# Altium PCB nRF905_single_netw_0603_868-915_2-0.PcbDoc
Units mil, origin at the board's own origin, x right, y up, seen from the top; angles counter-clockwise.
Board outline 720.03 x 705.03 mil, 2 copper layers (Top Layer, Bottom Layer); 19 components, 22 nets, 70 pads, 44 vias.
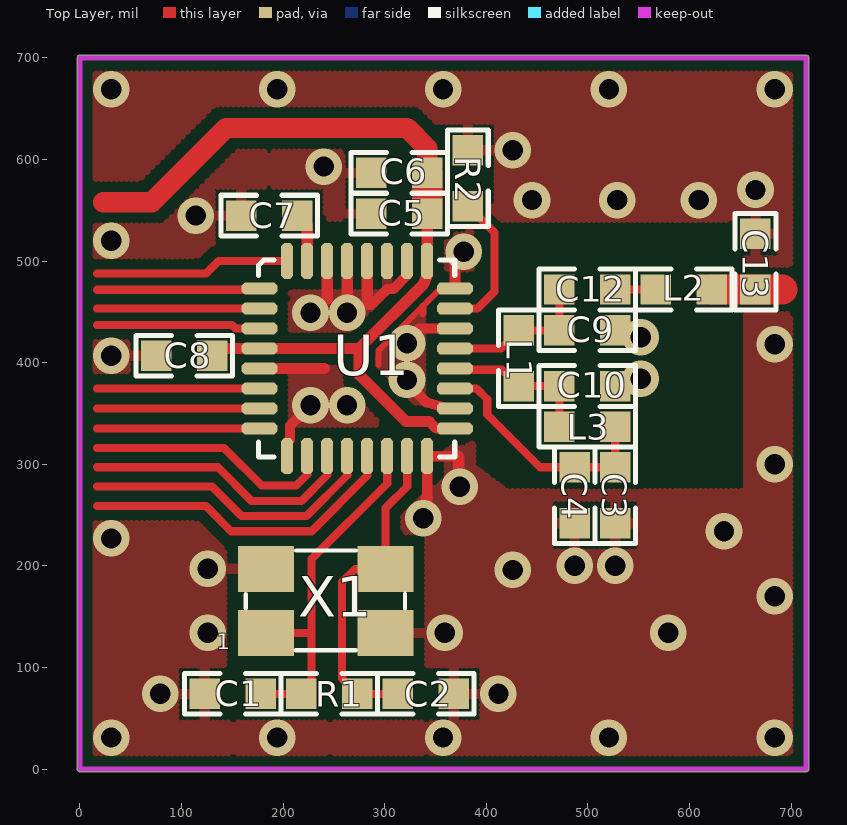
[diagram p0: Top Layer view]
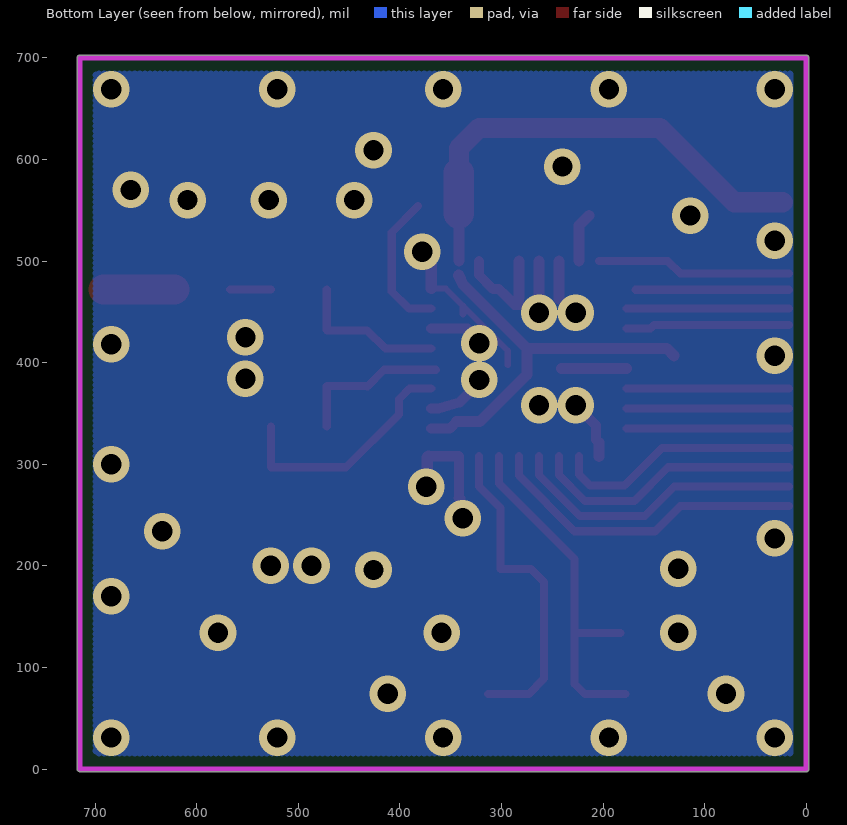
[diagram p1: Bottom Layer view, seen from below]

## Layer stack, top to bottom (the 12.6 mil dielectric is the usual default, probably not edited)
Top Layer: signal copper 1.4
Dielectric: core 12.6, FR-4, Dk 4.8
Bottom Layer: signal copper 1.4

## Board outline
-2.52,0 ccw(c0,0) 0,-2.52 715,-2.52 ccw(c715,0) 717.51,0 717.51,700 ccw(c715,700) 715,702.52 0,702.52 ccw(c0,700) -2.52,700

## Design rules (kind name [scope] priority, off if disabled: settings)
Clearance [All] p1: gap=6
ComponentClearance [All] p1: gap=10 collisioncheckmode=3 verticalgap=10
MinimumAnnularRing [All] p1: minimumring=8
PolygonConnect PolygonConnect_1 [IsVia And InNet(GND)] p1: connectstyle=Direct reliefconductorwidth=10 reliefentries=4 polygonreliefangle="90 Angle"
PolygonConnect [All] p2: connectstyle=Direct reliefconductorwidth=10 reliefentries=4 polygonreliefangle="90 Angle"
RoutingVias [All] p1: holewidth=20 width=36 viastyle="Through Hole" minholewidth=15 minwidth=30 maxholewidth=30 maxwidth=50
SolderMaskExpansion [All] p1: expansion=4
TestPointUsage [All] p1: valid=0 allowmultiple=FALSE
Testpoint [All] p1: side=15 testpointundercomponent=TRUE minsize=40 maxsize=100 preferedsize=60 minholesize=0 maxholesize=40 preferedholesize=32 testpointgrid=1 style=1023 order=0-112345678
Width [All] p1: maxlimit=30 minlimit=6 preferedwidth=6
18 further rules are at their usual default settings.

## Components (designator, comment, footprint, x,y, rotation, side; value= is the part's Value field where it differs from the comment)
C1 "22pF" 0603s#1 178,74 r180 top
C2 "22pF" 0603s#1 368,74 r180 top
C3 "33pF" 0603s#1 527,297 r270 top
C4 "3.3nF" 0603s#1 487,297 r270 top
C5 "33pF" 0603s#1 341.9,546.69 r180 top
C6 "4.7nF" 0603s#1 341.9,586.69 r180 top
C7 "10nF" 0603s#2 213.79,544.79 r180 top
C8 "33pF" 0603s#1 130.11,406.79 r180 top
C9 "5.6pF" 0603s#1 472,432 r0 top
C10 "5.6pF" 0603s#1 527,377 r180 top
C12 "22pF" 0603s#1 472,472 r0 top
C13 "4.7pF" 0603s#1 665,472 r90 top
L1 "12nH" 0603s#1 432,432 r270 top
L2 "10nH" 0603s#1 567,472 r0 top
L3 "12nH" 0603s#1 527,337 r180 top
R1 "1M" 0603s#1 218,74 r0 top
R2 "22K" 0603s#1 382,554 r90 top
U1 "nRF905" "QFN 5x5/32L" 273,404 r0 top
X1 "16 MHz" BT-XTAL 183,134 r0 top

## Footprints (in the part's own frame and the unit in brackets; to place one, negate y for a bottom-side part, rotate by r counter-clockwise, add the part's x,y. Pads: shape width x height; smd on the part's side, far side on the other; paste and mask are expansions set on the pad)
0603s#1 [mil]
  rect 30x30 smd: 1(0,0) 2(55,0)
  silkscreen extent -20,-20 75,20
0603s#2 [mil]
  rect 30x30 smd: 1(55,0) 2(0,0)
  silkscreen extent -20,-20 75,20
BT-XTAL [mm]
  rect 1.4x1.15 smd: 1(0,0) 2(2.996,0) 3(2.996,1.602) 4(0,1.602)
  silkscreen extent -0.5,-0.43 3.48,2.06
"QFN 5x5/32L" [mm]
  oct 0.9x0.3 smd: 1(-2.441,1.75) 2(-2.441,1.25) 3(-2.441,0.75) 4(-2.441,0.25) 5(-2.441,-0.25) 6(-2.441,-0.75) 7(-2.441,-1.25) 8(-2.441,-1.75) 17(2.441,-1.75) 18(2.441,-1.25) 19(2.441,-0.75) 20(2.441,-0.25) 21(2.441,0.25) 22(2.441,0.75) 23(2.441,1.25) 24(2.441,1.75)
  oct 0.3x0.9 smd: 9(-1.75,-2.441) 10(-1.25,-2.441) 11(-0.75,-2.441) 12(-0.25,-2.441) 13(0.25,-2.441) 14(0.75,-2.441) 15(1.25,-2.441) 16(1.75,-2.441) 25(1.75,2.441) 26(1.25,2.441) 27(0.75,2.441) 28(0.25,2.441) 29(-0.25,2.441) 30(-0.75,2.441) 31(-1.25,2.441) 32(-1.75,2.441)
  silkscreen extent -2.46,-2.46 2.44,2.46

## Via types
v1: diameter 36, hole 20, Top Layer to Bottom Layer, 44 vias

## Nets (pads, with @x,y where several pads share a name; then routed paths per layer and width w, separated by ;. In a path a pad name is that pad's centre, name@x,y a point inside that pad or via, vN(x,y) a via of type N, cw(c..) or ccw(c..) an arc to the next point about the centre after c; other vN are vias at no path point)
GND: C1.2 C2.1 C3.2 C4.2 C5.2 C6.2 C7.1 C8.2 C9.2 C10.1 C13.2 R2.2 U1.5 U1.9 U1.16 U1.18 U1.22 U1.24 U1.26 U1.27 U1.28 U1.29 U1.30 X1.2 X1.4 | length 687.7
  Top Layer w6: 293.84,397.66 293.84,411.84 354.9,472.9 U1.24
  Top Layer w7: 337.89,448.06 337.89,455.68
  Top Layer w10: U1.9@204.1,321.1 206.88,323.88 206.88,337.88 v1(227,358) ; 281,457 287.13,457 296.43,466.29 302.53,472.39 308.39,472.39 322.21,486.21 U1.26 ; v1@319,383 341,361 362,354.79 U1.18 ; v1@319,419 333.53,433.53 U1.22 ; 341.9,266.9 U1.16 372.11,307.89
  Top Layer w11: U1.5 240.84,394.16 ; U1.9 U1.9@204.1,321.1 ; 243.47,462.53 U1.30 ; v1@263.16,458.16 U1.29 ; 282.84,463.84 U1.28 ; 341,266 341.9,266.9 ; U1.24 369.11,500.11 v1(378,509) ; 372.11,307.89 373,307 v1@373,278
  other v1: 31,31 194.25,31 357.5,31 520.75,31 684,31 79,74 412,74 126,134 359,134 579,134 684,170 426,196 126,197.07 487,200 527,200 31,227 634,234 338,247 374,278 684,300 263,358 322,383 552,384 31,406.79 684,418 322,419 552,425 227,449 263,449 31,520 114.11,544.79 445,560 529,560 609,560 665,570 240,593 426,609 31,669 194.25,669 357.5,669 520.75,669 684,669
NetC1_1: C1.1 R1.1 U1.14 X1.1 | length 354
  Top Layer w8: C1.1 R1.1 227.89,83.89 228,83.89 228,206.63 302.53,281.15 U1.14 ; X1.1 228,134
NetC2_2: C2.2 R1.2 U1.15 X1.3 | length 324.2
  Top Layer w8: C2.2 R1.2 258,89 258,184 271.07,197.07 X1.3 300.95,256.95 322.21,278.21 U1.15
NetC3_1: C3.1 C4.1 L3.1 U1.19 | length 238.9
  Top Layer w8: U1.19 390.53,374.47 401,364 401,348.86 452.86,297 C4.1 C3.1 L3.1
NetC7_2: C7.2 U1.31 | length 48.8
  Top Layer w11: C7.2 223.79,534.79 U1.31
NetC9_1: C9.1 C12.1 L1.1 U1.21 | length 150.4
  Top Layer w8: U1.21 414.34,413.84 432.22,431.72 471.72,431.72 C9.1 C12.1
NetC10_2: C10.2 L1.2 L3.2 U1.20 | length 154.6
  Top Layer w8: U1.20@364.28,393 415.5,393 L1.2@432,376.5 ; L1.2 C10.2 L3.2
NetC12_2: C12.2 L2.1 | length 40
  Top Layer w8: C12.2 L2.1
NetC13_1: C13.1 L2.2 | length 69.5
  Top Layer w30: L2.2 691.5,472
NetR2_1: R2.1 U1.23 | length 140.6
  Top Layer w8: U1.23 391.21,453.21 408,470 408,528 R2.1
NetU1_1: U1.1 | length 151
  Top Layer w8: 17,471.69 U1.1@168,471.69
NetU1_2: U1.2 | length 159.9
  Top Layer w8: 17,453.21 U1.2
NetU1_3: U1.3 | length 161.4
  Top Layer w8: 17,437.21 149.79,437.21 153.47,433.53 U1.3
NetU1_6: U1.6 | length 159.9
  Top Layer w8: 17,374.47 U1.6
NetU1_7: U1.7 | length 159.9
  Top Layer w8: 17,354.79 U1.7
NetU1_8: U1.8 | length 159.9
  Top Layer w8: 17,335.1 U1.8
NetU1_10: U1.10 | length 244.7
  Top Layer w8: 17,316 142,316 179,279 213,279 223.79,289.79 U1.10
NetU1_11: U1.11 | length 269.1
  Top Layer w8: 17,297 136,297 169,264 218,264 243.47,289.47 U1.11
NetU1_12: U1.12 | length 293.5
  Top Layer w8: 17,278 130,278 159,249 223,249 263.16,289.16 U1.12
NetU1_13: U1.13 | length 318
  Top Layer w8: 17,259 124,259 149,234 228,234 282.84,288.84 U1.13
NetU1_32: U1.32 | length 192.2
  Top Layer w8: 17,487.69 124,487.69 136.42,500.11 U1.32
VDD: C5.1 C6.1 C8.1 U1.4 U1.17 U1.25 | length 857.1
  Top Layer w10: 344,342 350.9,335.1 U1.17
  Top Layer w11: C8.1 137.16,413.84 274.84,413.84 ; U1.25 C5.1 ; U1.25@342,486 338,477 274.84,413.84 ; 344,342 321,342 274.84,388.16 274.84,413.84
  Top Layer w20: 23,558 71,558 144,631 322,631 341.9,611.1 C6.1
  Top Layer w30: C5.1 C6.1

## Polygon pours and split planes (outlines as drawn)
GND on Top Layer "Top Layer-GND 1" (hatched 90Degree grid 5 track 7, remove dead copper, pour order 1001): 382,539.85 382,215 699,215 699,555 382,555
GND on Top Layer "Top Layer-GND" (hatched 90Degree grid 5 track 7, remove dead copper, pour order 1000): 715,214 382,214 382,556 715,556 715,700 0,700 0,1 715,1
GND on Bottom Layer "Bottom Layer-GND 1" (hatched 90Degree grid 5 track 7, remove dead copper, pour order 1003): 0,0 669,0 669,700 0,700
GND on Bottom Layer "Bottom Layer-GND" (hatched 90Degree grid 5 track 7, remove dead copper, pour order 1002): 654,0 654,700 715,700 715,0

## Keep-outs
Keep-Out Layer:
  lines w5: 0,0 715,0 715,700 0,700 0,0

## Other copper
Top Layer:
  pour cut-out: 625,541 385,541 387,298 420,273 656,273 656,541
  pour cut-out: 237,542 237,507 328,507 328,542

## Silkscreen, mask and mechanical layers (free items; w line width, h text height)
Mechanical 1:
  lines w5: 0,0 0,700 715,700 715,0 0,0
  text "GND" at -42,610 h12
  text "VDD" at -42,552 h12
  text "TXEN" at -54,482 h12
  text "TRX_CE" at -78,466 h12
  text "50 ohm RF I/O" at 725,465 h12
  text "PWR_UP" at -78,448 h12
  text "uPCLK" at -66,431 h12
  text "CD" at -30,369 h12
  text "AM" at -30,349 h12
  text "DR" at -30,327 h12
  text "MISO" at -52,310 h12
  text "MOSI" at -50,291 h12
  text "SCK" at -42,272 h12
  text "CSN" at -42,253 h12
Mechanical 2:
  lines w5: 13,-55 13,-45 ; 63,-66.67 13,-50 ; 63,-33.33 13,-50 ; 145.73,-50 13,-50 ; 569.27,-50 702,-50 ; 652,-66.67 702,-50 ; 652,-33.33 702,-50 ; 702,-55 702,-45 ; 748.33,63 765,13 ; 748.33,637 765,687 ; 760,13 770,13 ; 760,687 770,687 ; 765,138.23 765,13 ; 765,561.77 765,687 ; 781.67,63 765,13 ; 781.67,637 765,687
  text "674 (mil)" at 795.99,148.23 h50 r90
  text "689 (mil)" at 155.73,-80.99 h50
